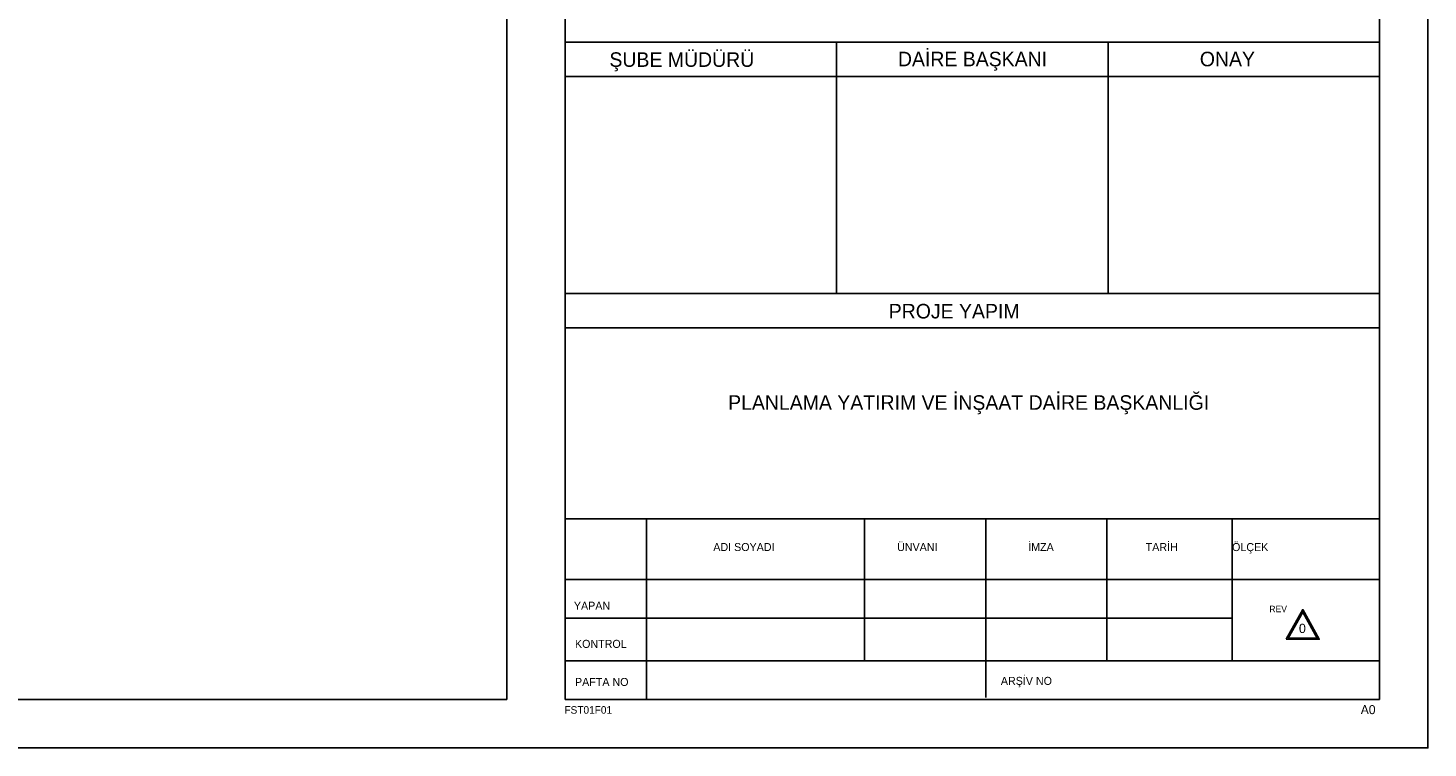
# Model space of a CAD drawing. Extents: x -10 to 1145, y -10 to 821.
# Drawn here: x 856.2 to 1145, y -10 to 138.4 of the extents above; entities that cross this region are included whole.
import ezdxf

# ---------------------------------------------------------------- set-up
doc = ezdxf.new("R2010")
doc.units = 0
for name, color, linetype in [('Level 1', 7, 'Continuous'), ('Level 50', 7, 'Continuous'), ('Level 51', 7, 'Continuous'), ('Level 6', 7, 'Continuous'), ('Level 7', 7, 'Continuous')]:
    doc.layers.add(name, color=color, linetype=linetype)

msp = doc.modelspace()

# ---------------------------------------------------------------- linework, layer by layer
at = {"layer": 'Level 50'}
msp.add_lwpolyline([(0, 0), (955, 0), (955, 811), (0, 811)], close=True, dxfattribs=at)
at = {"layer": 'Level 51'}
msp.add_lwpolyline([(-10, -10), (1145, -10), (1145, 821), (-10, 821)], close=True, dxfattribs=at)
at = {"layer": 'Level 6'}
for p, q in [((967.03, 0), (967.03, 262.93)), ((1135, 0), (1135, 262.93)), ((1135, 0), (1135, 262.93)), ((1135, 0), (1135, 262.93)), ((1135, 0), (1135, 262.93)), ((967.03, 135.51), (1135, 135.51)), ((967.03, 135.51), (1135, 135.51)), ((967.03, 135.51), (1135, 135.51)), ((967.03, 135.51), (1135, 135.51)), ((1023.03, 83.68), (1023.03, 135.51)), ((1079.03, 83.68), (1079.03, 135.51)), ((967.03, 128.43), (1135, 128.43)), ((967.03, 128.43), (1135, 128.43)), ((967.03, 128.43), (1135, 128.43)), ((967.03, 83.68), (1135, 83.68)), ((967.03, 83.68), (1135, 83.68)), ((967.03, 83.68), (1135, 83.68)), ((967.03, 83.68), (1135, 83.68)), ((967.03, 76.65), (1135, 76.65)), ((967.03, 37.27), (1135, 37.27)), ((967.03, 37.27), (1135, 37.27)), ((967.03, 37.27), (1135, 37.27)), ((967.03, 37.27), (1135, 37.27)), ((983.79, 0), (983.79, 37.13)), ((1028.79, 8.05), (1028.79, 37.13)), ((1053.79, 0.39), (1053.79, 37.13)), ((1078.79, 8.01), (1078.79, 37.13)), ((1104.62, 37.37), (1104.62, 8.07)), ((966.89, 24.76), (1134.87, 24.76)), ((967.03, 16.75), (1104.62, 16.75)), ((967.03, 7.98), (1134.87, 7.98)), ((967.03, 0), (1135, 0)), ((967.03, 0), (1135, 0)), ((967.03, 0), (1135, 0)), ((967.03, 0), (1135, 0))]:
    msp.add_line(p, q, dxfattribs=at)
at = {"layer": 'Level 7'}
for points in [[(1115.73, 12.41), (1119.15, 18.53), (1122.56, 12.41)], [(1115.73, 12.41), (1119.15, 18.53), (1122.56, 12.41)], [(1115.73, 12.41), (1119.15, 18.53), (1122.56, 12.41)], [(1115.73, 12.41), (1119.15, 18.53), (1122.56, 12.41)], [(1116.15, 12.66), (1119.15, 18.02), (1122.14, 12.66)], [(1116.15, 12.66), (1119.15, 18.02), (1122.14, 12.66)], [(1116.15, 12.66), (1119.15, 18.02), (1122.14, 12.66)], [(1116.15, 12.66), (1119.15, 18.02), (1122.14, 12.66)]]:
    msp.add_lwpolyline(points, close=True, dxfattribs=at)

# ---------------------------------------------------------------- texts
at = {"layer": 'Level 1'}
msp.add_text('0', height=1.92, dxfattribs=at).set_placement((1118.38, 13.7))
at = {"layer": 'Level 7'}
for s, height, p in [('ŞUBE MÜDÜRÜ', 3, (976.17, 130.43)), ('DAİRE BAŞKANI', 3, (1035.67, 130.55)), ('ONAY', 3, (1097.94, 130.55)), ('PROJE YAPIM', 3, (1033.78, 78.56)), ('PLANLAMA YATIRIM VE İNŞAAT DAİRE BAŞKANLIĞI', 3, (1000.65, 59.73)), ('ADI SOYADI', 1.65, (997.59, 30.61)), ('ÜNVANI', 1.65, (1035.5, 30.61)), ('İMZA', 1.65, (1062.54, 30.61)), ('TARİH', 1.65, (1086.77, 30.61)), ('ÖLÇEK', 1.65, (1104.59, 30.6)), ('YAPAN', 1.65, (968.84, 18.51)), ('REV', 1.32, (1112.28, 18)), ('KONTROL', 1.65, (969.06, 10.64)), ('PAFTA NO', 1.65, (969.07, 2.79)), ('ARŞİV NO', 1.65, (1056.9, 3.01)), ('FST01F01', 1.555, (966.89, -2.93)), ('A0', 1.866, (1131.13, -3.02))]:
    msp.add_text(s, height=height, dxfattribs=at).set_placement(p)

doc.saveas('drawing.dxf')
